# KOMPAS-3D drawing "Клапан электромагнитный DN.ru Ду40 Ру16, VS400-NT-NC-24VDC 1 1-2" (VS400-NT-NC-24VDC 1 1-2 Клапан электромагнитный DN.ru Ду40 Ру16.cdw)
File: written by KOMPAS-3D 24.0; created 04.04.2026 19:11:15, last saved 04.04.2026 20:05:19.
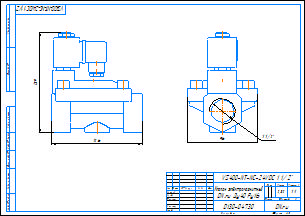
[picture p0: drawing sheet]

Document properties: c3d_UniqueCompID: ef56311e-7521-43dc-8291-0e6108b3d81d; Обозначение: VS400-ET-NC-220VAC 1; Наименование: Клапан электромагнитный DN.ru Ду25 Ру16; Автор: artio; Класс точности: c; Знак неуказанной шероховатости: Шероховатость не задана; Рассекать на разрезах: Да; c3d_UniqueCompID: ef56311e-7521-43dc-8291-0e6108b3d81d; Обозначение: VS400-ET-NC-220VAC 1-2; Наименование: Клапан электромагнитный DN.ru Ду15 Ру16; Автор: artio; Класс точности: c; Знак неуказанной шероховатости: Шероховатость не задана; Рассекать на разрезах: Да; c3d_UniqueCompID: ef56311e-7521-43dc-8291-0e6108b3d81d; Обозначение: VS400-ET-NC-220VAC 3-4; Наименование: Клапан электромагнитный DN.ru Ду20 Ру16; Автор: artio; Класс точности: c; Знак неуказанной шероховатости: Шероховатость не задана; Рассекать на разрезах: Да; c3d_UniqueCompID: ef56311e-7521-43dc-8291-0e6108b3d81d; Обозначение: VS400-ET-NC-220VAC 1 1-4; Наименование: Клапан электромагнитный DN.ru Ду32 Ру16; Автор: artio; Класс точности: c; Знак неуказанной шероховатости: Шероховатость не задана; Рассекать на разрезах: Да; c3d_UniqueCompID: ef56311e-7521-43dc-8291-0e6108b3d81d; Обозначение: VS400-ET-NC-220VAC 3-8; Наименование: Клапан электромагнитный DN.ru Ду10 Ру16; Автор: artio; Класс точности: c; Знак неуказанной шероховатости: Шероховатость не задана; Рассекать на разрезах: Да; c3d_UniqueCompID: ef56311e-7521-43dc-8291-0e6108b3d81d; Обозначение: VS400-ET-NC-220VAC 1 1-2; Наименование: Клапан электромагнитный DN.ru Ду40 Ру16; Автор: artio; Класс точности: c; Знак неуказанной шероховатости: Шероховатость не задана; Рассекать на разрезах: Да; Автор: artio; Форматы листов документа: A3; Полное имя файла: VS400-NT-NC-24VDC 1 1-2 Клапан электромагнитный DN.ru Ду40 Ру16.m3d; Масса: 2.321; Наименование: Клапан электромагнитный DN.ru Ду40 Ру16; Количество листов документа: 1; Примечание: D130-04730

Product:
- Body: Тело 1  | qty 1
    Масса: 4.144257
- Part/product: Клапан электромагнитный DN.ru Ду40 Ру16  | designation VS400-NT-NC-24VDC 1 1-2
    Масса: 2.321
    Раздел спецификации: Прочие изделия
    Примечание: D130-04730
    additional columns: ef56311e-7521-43dc-8291-0e6108b3d81d; VS400-ET-NC-220VAC 1 1-2; artio; c; Шероховатость не задана; Да

Views: Вид 1, Спереди
Referenced files in C:\Users\artio\OneDrive\Рабочий стол\Клапан электромагнитный DN.ru\VS400-ET-NC\VS400-ET-NC-24VDC\: VS400-ET-NC-24VDC 3-8 Клапан электромагнитный DN.ru Ду10 Ру16.m3d
Referenced files in C:\Users\artio\OneDrive\Рабочий стол\Клапан электромагнитный DN.ru\VS400-NT-NC\VS400-NT-NC-24VDC\: VS400-NT-NC-24VDC 1 1-2 Клапан электромагнитный DN.ru Ду40 Ру16.m3d
Referenced files in C:\Users\artio\OneDrive\Рабочий стол\Клапан электромагнитный DN.ru\VS400-ET-NC\: VS400-ET-NC-24VDC 3-8 Клапан электромагнитный DN.ru Ду10 Ру16.cdw
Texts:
  VS400-NT-NC-24VDC 1 1-2
  Клапан электромагнитный
  DN.ru Ду40 Ру16
  VS400-NT-NC-24VDC 1 1/2"
  VS400-NT-NC-24VDC 1 1/2"-
  Клапан электромагнитный DN.ru Ду40 Ру16
  VS400-NT-NC-24VDC 1 1-2 Клапан электромагнитный DN.ru Ду40 Ру16
Dimensions and other numbers on the sheet: 0; 3; 2; 4; 96; 1 1/2"; 1:1; 1; 2,32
